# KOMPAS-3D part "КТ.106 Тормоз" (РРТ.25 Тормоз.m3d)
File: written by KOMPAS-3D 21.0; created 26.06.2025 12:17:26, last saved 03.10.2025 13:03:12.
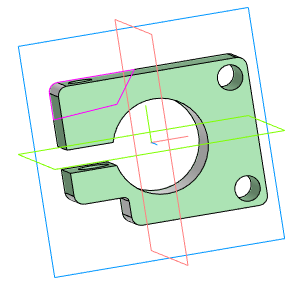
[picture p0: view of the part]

Document properties: Автор: User; Организация: User; Полное имя файла: C:\Users\User\Desktop\Ручной ротатор КД\Модели КД\РРТ.25 Тормоз.m3d

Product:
- Part/product: КТ.106 Тормоз
    Материал: Фторопласт-4  ГОСТ 10007-80 Е (density 2200 kg/m3)
    Масса: 0.02108
    Комментарий: User
  - Body: Тело 2
      Масса: 0.020559
  - Body: Тело 1
      Масса: 0.020559

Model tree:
1. Операция без истории:1
2. Эскиз:1
3. Элемент выдавливания:1
     Расстояние 1 = 15
4. Эскиз:2  (with: Операция без истории:1)
5. Элемент выдавливания:2  (with: Операция без истории:1)
     Расстояние 1 = 12.5
6. Элемент выдавливания:3  (with: Операция без истории:1)
     Расстояние 2 = 18
7. Зеркальный массив:2
8. Экземпляр ( 1 )
9. Экземпляр ( 2 )  (with: Элемент выдавливания:2)
10. Эскиз:3  (with: Элемент выдавливания:2)
11. Элемент выдавливания:4
     Расстояние 2 = 17
12. Эскиз:4  (with: Операция без истории:1)
13. Элемент выдавливания:8
     Расстояние 2 = 6.5
14. Скругление:3  (with: Элемент выдавливания:8)
     Радиус = 2
15. Скругление:4  (with: Элемент выдавливания:8)  (labels: Фторопласт-4  ГОСТ 10007-80 Е)
     Радиус = 1

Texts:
  Точка начала. Х
  Точка начала. Y
  Точка начала. Z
